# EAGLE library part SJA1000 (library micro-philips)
BASIC-CAN 2.0a Controller (former 82C200) Stand-alone CAN controller
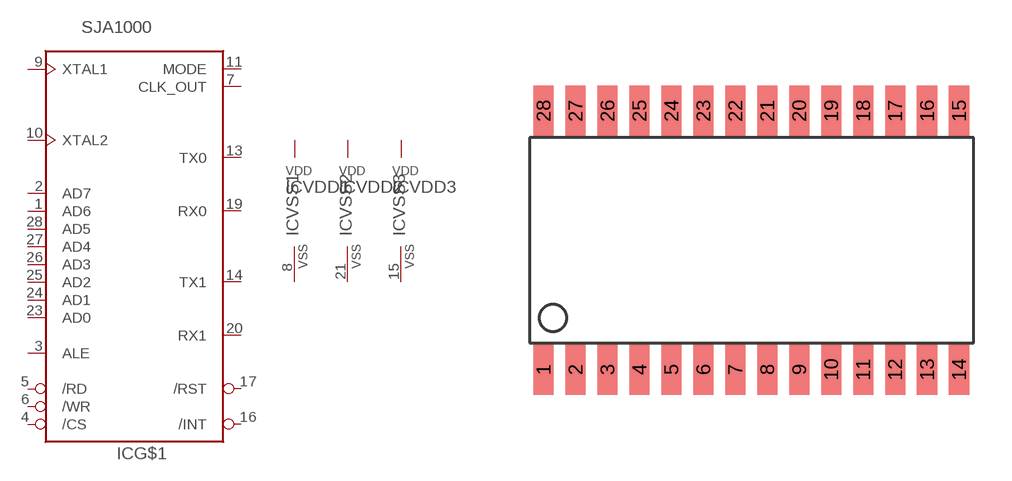
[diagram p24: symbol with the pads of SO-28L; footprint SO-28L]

Designator prefix IC; gates G$1=82C200 VDD1=VDD VDD2=VDD VDD3=VDD VSS1=VSS VSS2=VSS VSS3=VSS

## SJA1000T (MPN: SJA1000T/N1; OC_FARNELL: 1775880; OC_NEWARK: 52R2325)  [SO-28L]
1  G$1:AD6  hiz
2  G$1:AD7  hiz
3  G$1:ALE
4  G$1:/CS  in
5  G$1:/RD  in
6  G$1:/WR  in
7  G$1:CLK_OUT  out
8  VSS1:VSS  pwr
9  G$1:XTAL1  in
10  G$1:XTAL2  in
11  G$1:MODE  in
12  VDD3:VDD  pwr
13  G$1:TX0  out
14  G$1:TX1  out
15  VSS3:VSS  pwr
16  G$1:/INT  out
17  G$1:/RST  in
18  VDD2:VDD  pwr
19  G$1:RX0  in
20  G$1:RX1  in
21  VSS2:VSS  pwr
22  VDD1:VDD  pwr
23  G$1:AD0  hiz
24  G$1:AD1  hiz
25  G$1:AD2  hiz
26  G$1:AD3  hiz
27  G$1:AD4  hiz
28  G$1:AD5  hiz

## Footprint SO-28L (pad centres in mm)
Small Outline large
smd 0.8 x 2: 1 -8.89,-5.207; 2 -7.62,-5.207; 3 -6.35,-5.207; 4 -5.08,-5.207; 5 -3.81,-5.207; 6 -2.54,-5.207; 7 -1.27,-5.207; 8 0,-5.207; 9 1.27,-5.207; 10 2.54,-5.207; 11 3.81,-5.207; 12 5.08,-5.207; 13 6.35,-5.207; 14 7.62,-5.207; 15 7.62,5.08; 16 6.35,5.08; 17 5.08,5.08; 18 3.81,5.08; 19 2.54,5.08; 20 1.27,5.08; 21 0,5.08; 22 -1.27,5.08; 23 -2.54,5.08; 24 -3.81,5.08; 25 -5.08,5.08; 26 -6.35,5.08; 27 -7.62,5.08; 28 -8.89,5.08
